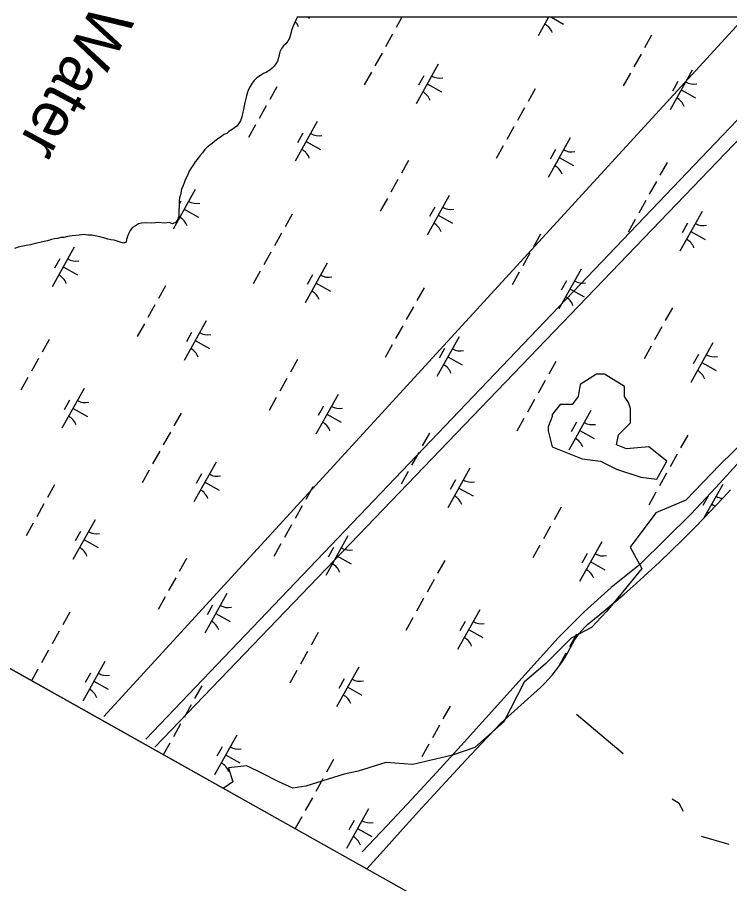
# Model space of a CAD drawing. Extents: x 3923531 to 3943530, y 207391 to 229799.
# Drawn here: x 3928152 to 3928937, y 212246 to 213200 of the extents above; entities that cross this region are included whole.
import ezdxf

# ---------------------------------------------------------------- set-up
doc = ezdxf.new("R2010")
doc.units = 0
for name, color, linetype in [('V-GRID-FRAM', 7, 'Continuous'), ('V-LEVE-TOET', 7, 'Continuous'), ('V-RIVR-EDGE', 7, 'Continuous'), ('V-RIVR-IDEN', 7, 'Continuous'), ('V-RRAP-FSHR', 7, 'Continuous'), ('V-TOPO-SHOR', 7, 'Continuous'), ('V-UTIL-LINE', 7, 'Continuous'), ('V-WETL-SWMP', 7, 'Continuous')]:
    doc.layers.add(name, color=color, linetype=linetype)

msp = doc.modelspace()

# ---------------------------------------------------------------- linework, layer by layer
at = {"layer": 'V-GRID-FRAM'}
msp.add_lwpolyline([(3941569.42, 222286.79), (3934196.47, 209089.08), (3926890.07, 213186.24), (3934009.8, 226348.12), (3941569.42, 222286.79)], dxfattribs=at)
at = {"layer": 'V-LEVE-TOET'}
for p, q in [((3928819.3, 212389.25), (3928768, 212432.64)), ((3928935.97, 212289.67), (3928905.5, 212298.37))]:
    msp.add_line(p, q, dxfattribs=at)
msp.add_lwpolyline([(3928885.76, 212325.84), (3928881.18, 212334.46), (3928873.45, 212339.41)], dxfattribs=at)
at = {"layer": 'V-RIVR-EDGE'}
msp.add_lwpolyline([(3928970.75, 212751.01), (3928925.96, 212707.4), (3928888.24, 212668.5), (3928855.23, 212654.36), (3928826.94, 212616.64), (3928839.91, 212593.06), (3928818.69, 212567.13), (3928801.01, 212545.91), (3928784.51, 212528.23), (3928762.11, 212516.45), (3928733.83, 212488.16), (3928710.25, 212468.12), (3928687.86, 212424.51), (3928656.03, 212396.22), (3928631.28, 212387.97), (3928587.66, 212377.36), (3928558.2, 212379.71), (3928527.55, 212370.29), (3928512.23, 212366.75), (3928469.79, 212353.78), (3928455.65, 212351.43), (3928440.33, 212358.5), (3928421.47, 212367.93), (3928404.96, 212376.18), (3928384.93, 212373.82), (3928389.64, 212358.5), (3928379.07, 212351.26)], dxfattribs=at)
at = {"layer": 'V-RRAP-FSHR'}
msp.add_lwpolyline([(3928948.8, 212712.45), (3928921.59, 212682.48), (3928894.16, 212653.39), (3928865.92, 212625.67), (3928837.23, 212597.25), (3928806.13, 212572.23), (3928776.43, 212545.4), (3928748.13, 212517.13), (3928721.45, 212487.72), (3928694.45, 212457.84), (3928667.85, 212427.97), (3928640.91, 212398.4), (3928613.92, 212368.88), (3928586.78, 212339.5), (3928559.34, 212310.39), (3928531.9, 212281.29)], dxfattribs=at)
at = {"layer": 'V-TOPO-SHOR'}
msp.add_lwpolyline([(3928820.99, 212793.65), (3928798.79, 212806.96), (3928789.92, 212806.96), (3928772.16, 212795.87), (3928769.94, 212782.55), (3928763.28, 212773.67), (3928749.96, 212773.67), (3928741.08, 212762.57), (3928741.08, 212760.35), (3928736.64, 212749.25), (3928736.64, 212744.81), (3928741.08, 212727.05), (3928774.38, 212713.74), (3928794.35, 212711.52), (3928812.11, 212702.64), (3928838.75, 212693.76), (3928856.51, 212691.54), (3928867.61, 212711.52), (3928847.63, 212727.05), (3928823.21, 212724.83), (3928812.11, 212729.27), (3928814.33, 212740.37), (3928827.65, 212753.69), (3928827.65, 212769.23), (3928825.43, 212775.89), (3928820.99, 212782.55)], close=True, dxfattribs=at)
at = {"layer": 'V-UTIL-LINE'}
for points in [[(3936636.37, 224015.9), (3936525.62, 224056.17), (3935321.28, 220766.16), (3935347.69, 220401.84), (3934871.29, 219561.15), (3934439.51, 219247.4), (3932085.86, 216616.76), (3928247.61, 212430.32)], [(3934948.13, 219998.51), (3933937.95, 218403.55), (3930512.92, 214727.55), (3928293.59, 212405.31)], [(3928303.68, 212396.77), (3930529.58, 214712.48), (3934263.4, 218684.83), (3934306.77, 218941.79), (3934562.09, 219352.8), (3934805.1, 219208.23)]]:
    msp.add_lwpolyline(points, dxfattribs=at)
at = {"layer": 'V-WETL-SWMP'}
for p, q in [((3928460.23, 213199.78), (3928459.13, 213197.21)), ((3929466.31, 213199.78), (3928460.23, 213199.78)), ((3928472.38, 213199.78), (3928474.12, 213198.81)), ((3928575.81, 213199.78), (3928569.46, 213188.41)), ((3928737.29, 213199.78), (3928725.84, 213179.28)), ((3928728.45, 213199.78), (3928728.37, 213199.63)), ((3928740.4, 213199.78), (3928753.74, 213192.33)), ((3928457.11, 213192.72), (3928455.69, 213189.21)), ((3928459.13, 213197.21), (3928457.11, 213192.72)), ((3928453.03, 213180.42), (3928452, 213176.9)), ((3928454.27, 213185.11), (3928453.03, 213180.42)), ((3928455.69, 213189.21), (3928454.27, 213185.11)), ((3928565.56, 213181.43), (3928557.76, 213167.46)), ((3928450.19, 213173.39), (3928447.8, 213170.68)), ((3928452, 213176.9), (3928450.19, 213173.39)), ((3928850.76, 213180.17), (3928842.95, 213166.21)), ((3928441.4, 213161.73), (3928440.57, 213158.61)), ((3928443.02, 213165.64), (3928441.4, 213161.73)), ((3928445.21, 213168.36), (3928443.02, 213165.64)), ((3928447.8, 213170.68), (3928445.21, 213168.36)), ((3928439.94, 213155.28), (3928438.71, 213151.57)), ((3928440.57, 213158.61), (3928439.94, 213155.28)), ((3928553.86, 213160.47), (3928546.05, 213146.51)), ((3928839.05, 213159.22), (3928831.25, 213145.25)), ((3928432.73, 213143.8), (3928430.15, 213141.68)), ((3928434.91, 213145.93), (3928432.73, 213143.8)), ((3928436.91, 213148.65), (3928434.91, 213145.93)), ((3928438.71, 213151.57), (3928436.91, 213148.65)), ((3928615.82, 213148.29), (3928591.43, 213104.63)), ((3928416.1, 213133.03), (3928413.12, 213130.13)), ((3928419.87, 213135.92), (3928416.1, 213133.03)), ((3928423.23, 213138.04), (3928419.87, 213135.92)), ((3928426.59, 213139.56), (3928423.23, 213138.04)), ((3928430.15, 213141.68), (3928426.59, 213139.56)), ((3928542.15, 213139.52), (3928534.35, 213125.55)), ((3928599.81, 213135.46), (3928593.96, 213124.98)), ((3928827.35, 213138.27), (3928819.54, 213124.3)), ((3928895.43, 213141.81), (3928871.05, 213098.16)), ((3928408.52, 213123.71), (3928406.91, 213120.4)), ((3928410.73, 213127.22), (3928408.52, 213123.71)), ((3928413.12, 213130.13), (3928410.73, 213127.22)), ((3928437.94, 213123.34), (3928430.13, 213109.37)), ((3928603.62, 213126.46), (3928619.34, 213117.68)), ((3928879.43, 213128.98), (3928873.58, 213118.51)), ((3928405.69, 213117.28), (3928404.66, 213113.37)), ((3928406.91, 213120.4), (3928405.69, 213117.28)), ((3928722.48, 213121.25), (3928714.68, 213107.29)), ((3928883.24, 213119.98), (3928898.96, 213111.2)), ((3928402.79, 213105.93), (3928402.16, 213102.22)), ((3928403.62, 213109.06), (3928402.79, 213105.93)), ((3928404.66, 213113.37), (3928403.62, 213109.06)), ((3928400.5, 213095.37), (3928399.45, 213090.28)), ((3928401.32, 213098.5), (3928400.5, 213095.37)), ((3928402.16, 213102.22), (3928401.32, 213098.5)), ((3928426.23, 213102.39), (3928418.43, 213088.42)), ((3928710.77, 213100.3), (3928702.97, 213086.33)), ((3928398.02, 213085.79), (3928395.81, 213082.68)), ((3928399.45, 213090.28), (3928398.02, 213085.79)), ((3928388.86, 213076.3), (3928385.3, 213073.99)), ((3928391.44, 213078.23), (3928388.86, 213076.3)), ((3928393.82, 213080.15), (3928391.44, 213078.23)), ((3928395.81, 213082.68), (3928393.82, 213080.15)), ((3928414.53, 213081.43), (3928406.72, 213067.47)), ((3928482.61, 213084.97), (3928458.23, 213041.32)), ((3928699.07, 213079.35), (3928691.27, 213065.38)), ((3928374.21, 213066.67), (3928369.85, 213063.59)), ((3928376.98, 213068.6), (3928374.21, 213066.67)), ((3928379.76, 213070.92), (3928376.98, 213068.6)), ((3928382.92, 213072.06), (3928379.76, 213070.92)), ((3928385.3, 213073.99), (3928382.92, 213072.06)), ((3928466.61, 213072.15), (3928460.76, 213061.67)), ((3928761.03, 213067.16), (3928736.64, 213023.51)), ((3928364.29, 213058.95), (3928360.71, 213056.25)), ((3928366.67, 213060.88), (3928364.29, 213058.95)), ((3928369.85, 213063.59), (3928366.67, 213060.88)), ((3928470.42, 213063.15), (3928486.14, 213054.37)), ((3928687.36, 213058.4), (3928679.56, 213044.43)), ((3928353.14, 213047.31), (3928350.33, 213043.42)), ((3928356.32, 213050.81), (3928353.14, 213047.31)), ((3928358.33, 213053.92), (3928356.32, 213050.81)), ((3928360.71, 213056.25), (3928358.33, 213053.92)), ((3928745.03, 213054.34), (3928739.17, 213043.86)), ((3928347.94, 213040.71), (3928345.93, 213037.2)), ((3928350.33, 213043.42), (3928347.94, 213040.71)), ((3928583.15, 213042.21), (3928575.35, 213028.25)), ((3928748.84, 213045.34), (3928764.55, 213036.56)), ((3928867.69, 213040.13), (3928859.89, 213026.16)), ((3928341.52, 213030.58), (3928339.5, 213025.89)), ((3928343.53, 213034.09), (3928341.52, 213030.58)), ((3928345.93, 213037.2), (3928343.53, 213034.09)), ((3928337.48, 213021.6), (3928335.85, 213017.7)), ((3928339.5, 213025.89), (3928337.48, 213021.6)), ((3928571.44, 213021.26), (3928563.64, 213007.29)), ((3928855.99, 213019.18), (3928848.18, 213005.21)), ((3928348.21, 213010.33), (3928323.82, 212966.67)), ((3928333.01, 213010.66), (3928331.75, 213004.4)), ((3928335.03, 213014.56), (3928333.01, 213010.66)), ((3928335.85, 213017.7), (3928335.03, 213014.56)), ((3928330.93, 213001.27), (3928330.48, 212997.74)), ((3928331.75, 213004.4), (3928330.93, 213001.27)), ((3928559.74, 213000.31), (3928551.94, 212986.34)), ((3928627.83, 213003.85), (3928603.44, 212960.2)), ((3928330.4, 212991.45), (3928329.97, 212988.32)), ((3928330.48, 212997.74), (3928330.4, 212991.45)), ((3928332.21, 212997.5), (3928330.44, 212994.34)), ((3928611.83, 212991.02), (3928605.97, 212980.55)), ((3928844.28, 212998.22), (3928836.48, 212984.26)), ((3928330.26, 212980.46), (3928328.24, 212976.17)), ((3928329.97, 212988.32), (3928329.91, 212983.61)), ((3928329.91, 212983.61), (3928330.26, 212980.46)), ((3928336.02, 212988.5), (3928351.73, 212979.72)), ((3928454.87, 212983.29), (3928447.07, 212969.33)), ((3928615.64, 212982.02), (3928631.35, 212973.24)), ((3928906.24, 212986.04), (3928881.86, 212942.39)), ((3928285.77, 212972.41), (3928282.21, 212970.49)), ((3928288.92, 212973.15), (3928285.77, 212972.41)), ((3928292.85, 212973.49), (3928288.92, 212973.15)), ((3928299.53, 212973.4), (3928292.85, 212973.49)), ((3928304.25, 212973.73), (3928299.53, 212973.4)), ((3928307.79, 212974.08), (3928304.25, 212973.73)), ((3928314.84, 212973.2), (3928307.79, 212974.08)), ((3928319.57, 212973.92), (3928314.84, 212973.2)), ((3928323.08, 212972.7), (3928319.57, 212973.92)), ((3928326.24, 212973.83), (3928323.08, 212972.7)), ((3928328.24, 212976.17), (3928326.24, 212973.83)), ((3928832.58, 212977.27), (3928824.77, 212963.3)), ((3928890.24, 212973.21), (3928884.39, 212962.74)), ((3928274.63, 212961.56), (3928273.41, 212958.43)), ((3928276.64, 212965.07), (3928274.63, 212961.56)), ((3928279.04, 212968.57), (3928276.64, 212965.07)), ((3928282.21, 212970.49), (3928279.04, 212968.57)), ((3928443.17, 212962.34), (3928435.36, 212948.37)), ((3928728.36, 212961.09), (3928720.56, 212947.12)), ((3928894.05, 212964.21), (3928909.76, 212955.43)), ((3928177.1, 212951.85), (3928171.98, 212950.74)), ((3928181.83, 212952.97), (3928177.1, 212951.85)), ((3928185.38, 212953.71), (3928181.83, 212952.97)), ((3928189.71, 212955.22), (3928185.38, 212953.71)), ((3928193.26, 212955.96), (3928189.71, 212955.22)), ((3928196.41, 212956.31), (3928193.26, 212955.96)), ((3928200.35, 212957.43), (3928196.41, 212956.31)), ((3928203.49, 212957.39), (3928200.35, 212957.43)), ((3928207.43, 212958.52), (3928203.49, 212957.39)), ((3928212.55, 212959.24), (3928207.43, 212958.52)), ((3928220.41, 212959.92), (3928212.55, 212959.24)), ((3928225.53, 212960.64), (3928220.41, 212959.92)), ((3928229.84, 212960.19), (3928225.53, 212960.64)), ((3928234.16, 212960.13), (3928229.84, 212960.19)), ((3928239.64, 212958.88), (3928234.16, 212960.13)), ((3928243.17, 212958.05), (3928239.64, 212958.88)), ((3928248.65, 212956.8), (3928243.17, 212958.05)), ((3928251.77, 212955.58), (3928248.65, 212956.8)), ((3928255.3, 212954.74), (3928251.77, 212955.58)), ((3928258.83, 212954.7), (3928255.3, 212954.74)), ((3928262.35, 212953.47), (3928258.83, 212954.7)), ((3928265.47, 212952.25), (3928262.35, 212953.47)), ((3928269, 212951.42), (3928265.47, 212952.25)), ((3928272.15, 212952.17), (3928269, 212951.42)), ((3928272.58, 212955.3), (3928272.15, 212952.17)), ((3928273.41, 212958.43), (3928272.58, 212955.3)), ((3928153.08, 212946.67), (3928149.14, 212945.55)), ((3928158.2, 212947.78), (3928153.08, 212946.67)), ((3928162.14, 212948.52), (3928158.2, 212947.78)), ((3928166.86, 212949.24), (3928162.14, 212948.52)), ((3928171.98, 212950.74), (3928166.86, 212949.24)), ((3928215.01, 212947.01), (3928190.62, 212903.36)), ((3928199.01, 212934.19), (3928193.15, 212923.71)), ((3928431.46, 212941.39), (3928423.66, 212927.42)), ((3928716.66, 212940.14), (3928708.86, 212926.17)), ((3928202.82, 212925.19), (3928218.53, 212916.41)), ((3928493.42, 212929.2), (3928469.04, 212885.55)), ((3928419.76, 212920.44), (3928411.95, 212906.47)), ((3928477.42, 212916.38), (3928471.57, 212905.9)), ((3928704.95, 212919.19), (3928697.15, 212905.22)), ((3928773.04, 212922.72), (3928748.66, 212879.07)), ((3928315.54, 212904.25), (3928307.74, 212890.29)), ((3928481.23, 212907.38), (3928496.94, 212898.6)), ((3928757.04, 212909.9), (3928751.19, 212899.42)), ((3928600.09, 212902.17), (3928592.28, 212888.2)), ((3928760.85, 212900.9), (3928776.56, 212892.12)), ((3928303.84, 212883.3), (3928296.04, 212869.33)), ((3928588.38, 212881.22), (3928580.58, 212867.25)), ((3928873.58, 212879.97), (3928865.77, 212866)), ((3928360.22, 212865.89), (3928335.84, 212822.24)), ((3928292.13, 212862.35), (3928284.33, 212848.38)), ((3928576.68, 212860.26), (3928568.87, 212846.3)), ((3928861.87, 212859.01), (3928854.07, 212845.05)), ((3928344.22, 212853.06), (3928338.37, 212842.59)), ((3928638.64, 212848.08), (3928614.25, 212804.43)), ((3928187.27, 212845.33), (3928179.46, 212831.36)), ((3928348.03, 212844.06), (3928363.74, 212835.28)), ((3928564.97, 212839.31), (3928557.17, 212825.34)), ((3928850.17, 212838.06), (3928842.36, 212824.09)), ((3928918.26, 212841.6), (3928893.87, 212797.95)), ((3928622.63, 212835.25), (3928616.78, 212824.78)), ((3928902.25, 212828.77), (3928896.4, 212818.3)), ((3928175.56, 212824.38), (3928167.76, 212810.41)), ((3928460.76, 212823.13), (3928452.95, 212809.16)), ((3928626.44, 212826.25), (3928642.16, 212817.47)), ((3928745.3, 212821.04), (3928737.5, 212807.08)), ((3928906.06, 212819.77), (3928921.78, 212811)), ((3928163.86, 212803.43), (3928156.05, 212789.46)), ((3928449.05, 212802.18), (3928441.25, 212788.21)), ((3928733.6, 212800.09), (3928725.79, 212786.12)), ((3928225.82, 212791.24), (3928201.43, 212747.59)), ((3928437.35, 212781.23), (3928429.54, 212767.26)), ((3928505.44, 212784.76), (3928481.05, 212741.11)), ((3928209.81, 212778.42), (3928203.96, 212767.94)), ((3928489.43, 212771.94), (3928483.58, 212761.46)), ((3928721.89, 212779.14), (3928714.09, 212765.17)), ((3928213.62, 212769.42), (3928229.34, 212760.64)), ((3928332.48, 212764.21), (3928324.68, 212750.24)), ((3928493.24, 212762.94), (3928508.96, 212754.16)), ((3928783.85, 212766.95), (3928759.46, 212723.3)), ((3928710.19, 212758.19), (3928702.38, 212744.22)), ((3928767.85, 212754.13), (3928762, 212743.65)), ((3928320.78, 212743.26), (3928312.97, 212729.29)), ((3928605.97, 212742.01), (3928598.17, 212728.04)), ((3928771.66, 212745.13), (3928787.37, 212736.35)), ((3928890.51, 212739.92), (3928882.71, 212725.95)), ((3928309.07, 212722.3), (3928301.27, 212708.34)), ((3928594.27, 212721.05), (3928586.46, 212707.08)), ((3928878.81, 212718.97), (3928871.01, 212705)), ((3928371.03, 212710.12), (3928346.64, 212666.47)), ((3928650.65, 212703.64), (3928626.26, 212659.99)), ((3928297.37, 212701.35), (3928289.56, 212687.38)), ((3928355.03, 212697.29), (3928349.18, 212686.82)), ((3928582.56, 212700.1), (3928574.76, 212686.13)), ((3928867.1, 212698.02), (3928859.3, 212684.05)), ((3928193.15, 212685.17), (3928185.35, 212671.2)), ((3928358.84, 212688.29), (3928374.55, 212679.51)), ((3928634.65, 212690.81), (3928628.79, 212680.34)), ((3928929.06, 212685.83), (3928908.38, 212648.81)), ((3927795.94, 212678.26), (3928536.98, 212262.71)), ((3928477.69, 212683.08), (3928469.89, 212669.12)), ((3928638.46, 212681.81), (3928654.17, 212673.04)), ((3928855.4, 212677.06), (3928847.6, 212663.1)), ((3928929.4, 212671.03), (3928937.43, 212679.88)), ((3928913.06, 212673), (3928907.21, 212662.53)), ((3928921.19, 212662.33), (3928929.4, 212671.03)), ((3928181.45, 212664.22), (3928173.64, 212650.25)), ((3928465.99, 212662.13), (3928458.19, 212648.16)), ((3928751.18, 212660.88), (3928743.38, 212646.91)), ((3928909.16, 212649.61), (3928921.19, 212662.33)), ((3928916.87, 212664), (3928920.73, 212661.85)), ((3928237.83, 212646.8), (3928213.44, 212603.15)), ((3928896.96, 212637.04), (3928909.16, 212649.61)), ((3928169.74, 212643.27), (3928161.94, 212629.3)), ((3928454.28, 212641.18), (3928446.48, 212627.21)), ((3928739.48, 212639.93), (3928731.68, 212625.96)), ((3928884.59, 212624.63), (3928896.96, 212637.04)), ((3928221.83, 212633.98), (3928215.97, 212623.5)), ((3928516.24, 212628.99), (3928491.86, 212585.34)), ((3928225.64, 212624.98), (3928241.35, 212616.2)), ((3928442.58, 212620.23), (3928434.78, 212606.26)), ((3928727.77, 212618.98), (3928719.97, 212605.01)), ((3928795.86, 212622.51), (3928771.48, 212578.86)), ((3928872.06, 212612.39), (3928884.59, 212624.63)), ((3928500.24, 212616.17), (3928494.39, 212605.69)), ((3928779.86, 212609.69), (3928774.01, 212599.21)), ((3928859.38, 212600.31), (3928872.06, 212612.39)), ((3928338.36, 212604.05), (3928330.56, 212590.08)), ((3928504.05, 212607.17), (3928519.77, 212598.39)), ((3928622.91, 212601.96), (3928615.1, 212587.99)), ((3928783.67, 212600.69), (3928799.38, 212591.91)), ((3928846.54, 212588.4), (3928859.38, 212600.31)), ((3928326.66, 212583.09), (3928318.86, 212569.12)), ((3928611.2, 212581.01), (3928603.4, 212567.04)), ((3928833.54, 212576.66), (3928846.54, 212588.4)), ((3928820.39, 212565.09), (3928833.54, 212576.66)), ((3928314.95, 212562.14), (3928307.15, 212548.17)), ((3928383.04, 212565.68), (3928358.66, 212522.03)), ((3928807.09, 212553.7), (3928820.39, 212565.09)), ((3928367.04, 212552.85), (3928361.19, 212542.38)), ((3928599.5, 212560.06), (3928591.69, 212546.09)), ((3928793.64, 212542.48), (3928807.09, 212553.7)), ((3928210.09, 212545.12), (3928202.28, 212531.16)), ((3928370.85, 212543.85), (3928386.56, 212535.07)), ((3928661.46, 212547.87), (3928637.07, 212504.22)), ((3928780.04, 212531.44), (3928793.64, 212542.48)), ((3928587.79, 212539.1), (3928579.99, 212525.14)), ((3928645.46, 212535.04), (3928639.6, 212524.57)), ((3928198.38, 212524.17), (3928190.58, 212510.2)), ((3928483.58, 212522.92), (3928475.78, 212508.95)), ((3928649.26, 212526.04), (3928664.98, 212517.26)), ((3928770.97, 212521.52), (3928773.82, 212524.99)), ((3928773.82, 212524.99), (3928776.85, 212528.29)), ((3928776.85, 212528.29), (3928780.04, 212531.44)), ((3928768.12, 212520.84), (3928760.32, 212506.87)), ((3928763.58, 212510.31), (3928765.84, 212514.18)), ((3928765.84, 212514.18), (3928768.31, 212517.92)), ((3928768.31, 212517.92), (3928770.97, 212521.52)), ((3928758.61, 212500.9), (3928761.52, 212506.33)), ((3928761.52, 212506.33), (3928763.58, 212510.31)), ((3928186.68, 212503.22), (3928178.87, 212489.25)), ((3928471.87, 212501.97), (3928464.07, 212488)), ((3928756.42, 212499.88), (3928748.61, 212485.92)), ((3928752.18, 212490.4), (3928755.5, 212495.59)), ((3928755.5, 212495.59), (3928758.61, 212500.9)), ((3928248.64, 212491.03), (3928224.25, 212447.38)), ((3928528.26, 212484.55), (3928503.87, 212440.9)), ((3928744.95, 212480.44), (3928748.66, 212485.35)), ((3928748.66, 212485.35), (3928752.18, 212490.4)), ((3928174.97, 212482.27), (3928167.93, 212469.66)), ((3928232.64, 212478.21), (3928226.78, 212467.73)), ((3928460.17, 212481.02), (3928452.37, 212467.05)), ((3928736.96, 212471.07), (3928741.04, 212475.67)), ((3928741.04, 212475.67), (3928744.95, 212480.44)), ((3928236.44, 212469.21), (3928252.16, 212460.43)), ((3928512.25, 212471.73), (3928506.4, 212461.25)), ((3928728.26, 212462.35), (3928732.7, 212466.62)), ((3928732.7, 212466.62), (3928736.96, 212471.07)), ((3928355.3, 212464), (3928347.5, 212450.03)), ((3928516.06, 212462.73), (3928531.78, 212453.95)), ((3928685.06, 212423.38), (3928728.26, 212462.35)), ((3928343.6, 212443.05), (3928335.79, 212429.08)), ((3928628.79, 212441.8), (3928620.99, 212427.83)), ((3928331.89, 212422.1), (3928324.09, 212408.13)), ((3928617.09, 212420.84), (3928609.28, 212406.88)), ((3928663.07, 212400.33), (3928685.06, 212423.38)), ((3928393.85, 212409.91), (3928369.47, 212366.26)), ((3928320.19, 212401.14), (3928313.01, 212388.3)), ((3928605.38, 212399.89), (3928597.58, 212385.92)), ((3928641.24, 212377.11), (3928663.07, 212400.33)), ((3928377.85, 212397.08), (3928372, 212386.61)), ((3928381.66, 212388.08), (3928397.37, 212379.3)), ((3928500.52, 212382.88), (3928492.71, 212368.91)), ((3928619.58, 212353.75), (3928641.24, 212377.11)), ((3928488.81, 212361.92), (3928481.01, 212347.96)), ((3928598.08, 212330.23), (3928619.58, 212353.75)), ((3928477.11, 212340.97), (3928469.3, 212327)), ((3928539.06, 212328.78), (3928514.68, 212285.13)), ((3928576.74, 212306.56), (3928598.08, 212330.23)), ((3928465.4, 212320.02), (3928458.1, 212306.94)), ((3928523.06, 212315.96), (3928517.21, 212305.48)), ((3928526.87, 212306.96), (3928542.59, 212298.18)), ((3928555.58, 212282.75), (3928576.74, 212306.56)), ((3928536.98, 212262.71), (3928555.58, 212282.75))]:
    msp.add_line(p, q, dxfattribs=at)
for centre, start, end in [((3928445.14, 213183.35), 20.03808, 42.11616), ((3928724.76, 213176.88), 20.03808, 61.58174), ((3928617.3, 213150.46), 240.03808, 281.58174), ((3928896.92, 213143.98), 240.03808, 281.58174), ((3928590.36, 213102.23), 20.03808, 61.58174), ((3928869.98, 213095.75), 20.03808, 61.58174), ((3928484.1, 213087.14), 240.03808, 281.58174), ((3928457.16, 213038.92), 20.03808, 61.58174), ((3928762.51, 213069.33), 240.03808, 281.58174), ((3928735.57, 213021.11), 20.03808, 61.58174), ((3928349.69, 213012.5), 240.03808, 281.58174), ((3928629.31, 213006.02), 240.03808, 281.58174), ((3928322.75, 212964.27), 20.03808, 61.58174), ((3928602.37, 212957.79), 20.03808, 61.58174), ((3928907.73, 212988.21), 240.03808, 281.58174), ((3928880.79, 212939.98), 20.03808, 61.58174), ((3928216.49, 212949.18), 240.03808, 281.58174), ((3928189.55, 212900.96), 20.03808, 61.58174), ((3928494.91, 212931.37), 240.03808, 281.58174), ((3928774.53, 212924.9), 240.03808, 281.58174), ((3928467.97, 212883.15), 20.03808, 61.58174), ((3928747.59, 212876.67), 20.03808, 61.58174), ((3928361.71, 212868.06), 240.03808, 281.58174), ((3928334.77, 212819.83), 20.03808, 61.58174), ((3928640.12, 212850.25), 240.03808, 281.58174), ((3928919.74, 212843.77), 240.03808, 281.58174), ((3928613.18, 212802.02), 20.03808, 61.58174), ((3928892.8, 212795.54), 20.03808, 61.58174), ((3928227.3, 212793.41), 240.03808, 281.58174), ((3928506.92, 212786.94), 240.03808, 281.58174), ((3928200.36, 212745.19), 20.03808, 61.58174), ((3928479.98, 212738.71), 20.03808, 61.58174), ((3928785.34, 212769.13), 240.03808, 281.58174), ((3928758.39, 212720.9), 20.03808, 61.58174), ((3928372.52, 212712.29), 240.03808, 281.58174), ((3928652.14, 212705.81), 240.03808, 281.58174), ((3928345.57, 212664.06), 20.03808, 61.58174), ((3928625.19, 212657.58), 20.03808, 61.58174), ((3928930.55, 212688), 240.03808, 264.48769), ((3928903.61, 212639.77), 55.49174, 61.58174), ((3928239.32, 212648.98), 240.03808, 281.58174), ((3928212.37, 212600.75), 20.03808, 61.58174), ((3928517.73, 212631.16), 240.03808, 281.58174), ((3928797.35, 212624.69), 240.03808, 281.58174), ((3928490.79, 212582.94), 20.03808, 61.58174), ((3928770.41, 212576.46), 20.03808, 61.58174), ((3928384.53, 212567.85), 240.03808, 281.58174), ((3928357.59, 212519.62), 20.03808, 61.58174), ((3928662.94, 212550.04), 240.03808, 281.58174), ((3928636, 212501.81), 20.03808, 61.58174), ((3928250.12, 212493.2), 240.03808, 281.58174), ((3928529.74, 212486.73), 240.03808, 281.58174), ((3928223.18, 212444.98), 20.03808, 61.58174), ((3928502.8, 212438.5), 20.03808, 61.58174), ((3928395.34, 212412.08), 240.03808, 281.58174), ((3928368.39, 212363.85), 20.03808, 61.58174), ((3928540.55, 212330.96), 240.03808, 281.58174), ((3928513.61, 212282.73), 20.03808, 61.58174)]:
    msp.add_arc(centre, 17.62, start, end, dxfattribs=at)

# ---------------------------------------------------------------- texts
at = {"layer": 'V-RIVR-IDEN'}
msp.add_text('Water', height=50, rotation=241.58945, dxfattribs=at).set_placement((3928237.23, 213217.56))

doc.saveas('drawing.dxf')
